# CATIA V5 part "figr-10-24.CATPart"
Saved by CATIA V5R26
Part number: Part1
Bounding box of the stored display mesh (mm): x -180.516 to 0, y -36.805 to 65.824, z 0 to 36.805
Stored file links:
  D:\_Deepak\CATIA\CATIA V5-6R2016_Deepak\Resources\Part files\Partfiles\c10_catia_v5_6r2016_prt\figr-10-24.CATPart
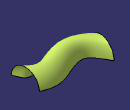
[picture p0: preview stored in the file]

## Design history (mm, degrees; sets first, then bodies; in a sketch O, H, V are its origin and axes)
Set1
  Sweep1: type Unspec, Profile Sketch2, Guide Sketch1
Body1 (main body)
  Sketch1 on xy-plane, origin (0, 0, 0), H (1, 0, 0), V (0, 1, 0)
    spline S1 through (0, 0) (-31.5913, 14.7273) (-94.8038, 0) (-174.5181, 29.5113)
    point P1 (0, 0)
    point P2 (-94.8038, 0)
    coincidence: P1 O, P2 H
  Sketch2 on yz-plane, origin (0, 0, 0), H (0, 1, 0), V (0, 0, 1)
    arc A1 centre (0, 0) radius 36.8048 from (36.8048, 0) to (-36.8048, 0) ccw
    point P1 (-36.8048, 0)
    point P2 (36.8048, 0)
    coincidence: P1 H, P2 H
